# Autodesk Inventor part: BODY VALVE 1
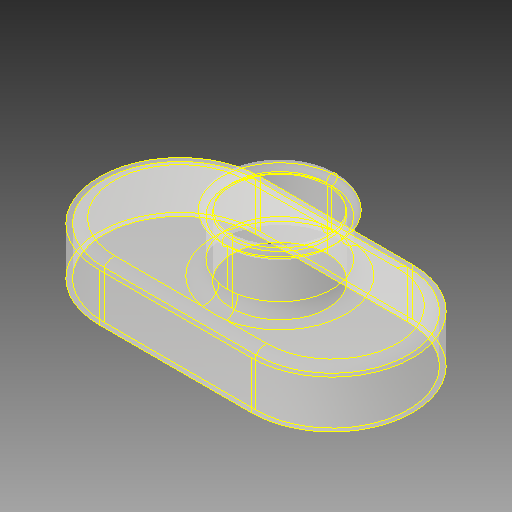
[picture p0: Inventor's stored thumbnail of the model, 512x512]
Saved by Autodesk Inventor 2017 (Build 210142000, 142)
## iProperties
Created: 2020-03
Part Number: BODY VALVE 1
Material: Generic
Document SubType Name: Modeling
Designer: user
Density: 1 g/cm^3
Appearance: Default
Author: user
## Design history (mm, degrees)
feature "Composite1"
body "Srf1"
